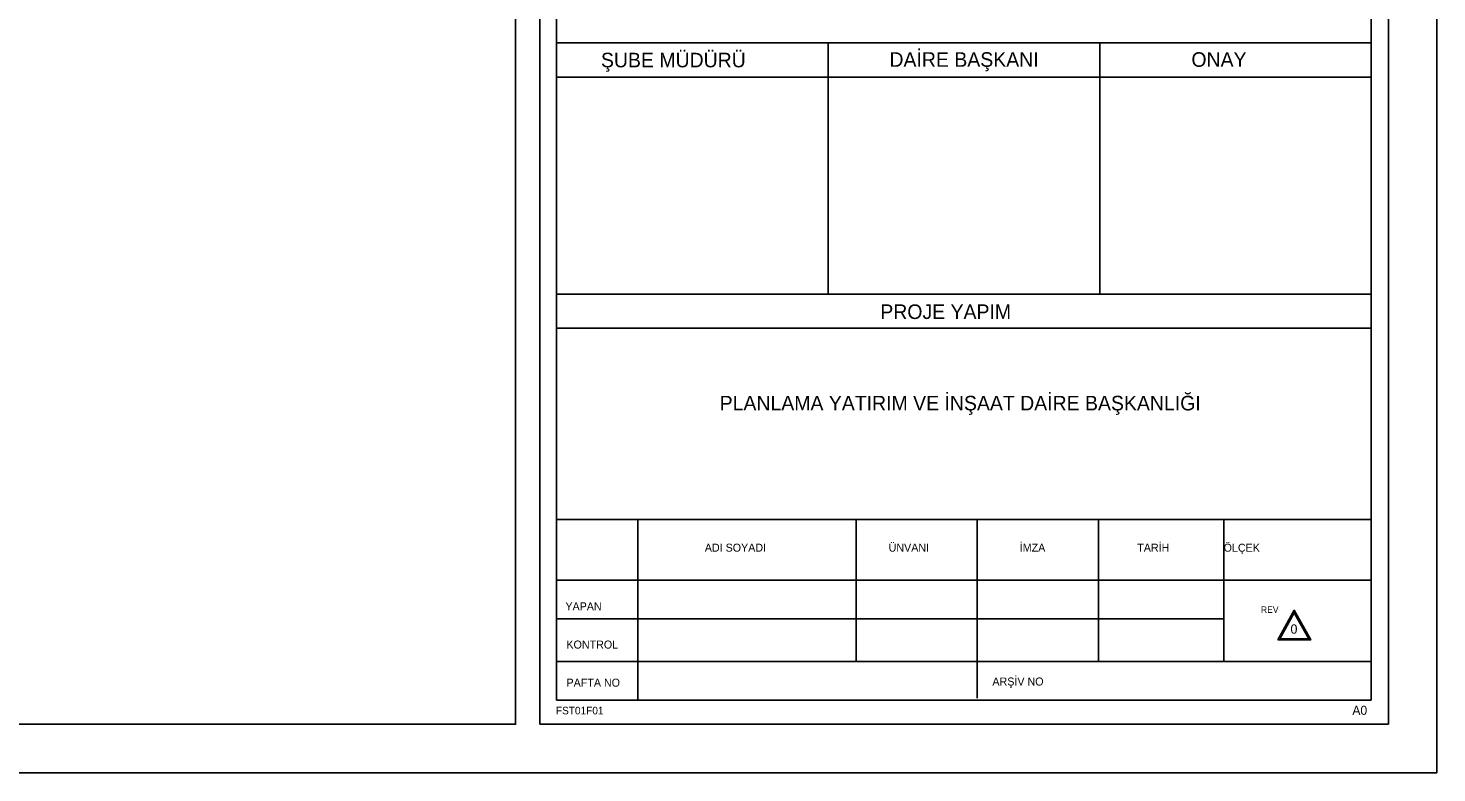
# Model space of a CAD drawing. Extents: x -17 to 1145, y -10 to 821.
# Drawn here: x 854.5 to 1145, y -10 to 143.5 of the extents above; entities that cross this region are included whole.
import ezdxf

# ---------------------------------------------------------------- set-up
doc = ezdxf.new("R2010")
doc.units = 0
for name, color, linetype in [('Level 1', 7, 'Continuous'), ('Level 50', 7, 'Continuous'), ('Level 51', 7, 'Continuous'), ('Level 6', 7, 'Continuous'), ('Level 7', 7, 'Continuous')]:
    doc.layers.add(name, color=color, linetype=linetype)

msp = doc.modelspace()

# ---------------------------------------------------------------- linework, layer by layer
at = {"layer": 'Level 1'}
for p, q in [((960, 0), (960, 287)), ((1135, 287), (1135, 0)), ((1135, 0), (960, 0))]:
    msp.add_line(p, q, dxfattribs=at)
at = {"layer": 'Level 50'}
msp.add_lwpolyline([(-7, 0), (955, 0), (955, 811), (-7, 811)], close=True, dxfattribs=at)
at = {"layer": 'Level 51'}
msp.add_lwpolyline([(-17, -10), (1145, -10), (1145, 821), (-17, 821)], close=True, dxfattribs=at)
at = {"layer": 'Level 6'}
for p, q in [((963.47, 4.97), (963.47, 267.9)), ((1131.45, 4.97), (1131.45, 267.9)), ((1131.45, 4.97), (1131.45, 267.9)), ((1131.45, 4.97), (1131.45, 267.9)), ((1131.45, 4.97), (1131.45, 267.9)), ((963.47, 140.48), (1131.45, 140.48)), ((963.47, 140.48), (1131.45, 140.48)), ((963.47, 140.48), (1131.45, 140.48)), ((963.47, 140.48), (1131.45, 140.48)), ((1019.47, 88.65), (1019.47, 140.48)), ((1075.47, 88.65), (1075.47, 140.48)), ((963.47, 133.4), (1131.45, 133.4)), ((963.47, 133.4), (1131.45, 133.4)), ((963.47, 133.4), (1131.45, 133.4)), ((963.47, 88.65), (1131.45, 88.65)), ((963.47, 88.65), (1131.45, 88.65)), ((963.47, 88.65), (1131.45, 88.65)), ((963.47, 88.65), (1131.45, 88.65)), ((963.47, 81.62), (1131.45, 81.62)), ((963.47, 42.24), (1131.45, 42.24)), ((963.47, 42.24), (1131.45, 42.24)), ((963.47, 42.24), (1131.45, 42.24)), ((963.47, 42.24), (1131.45, 42.24)), ((980.23, 4.97), (980.23, 42.1)), ((1025.23, 13.02), (1025.23, 42.1)), ((1050.23, 5.36), (1050.23, 42.1)), ((1075.23, 12.98), (1075.23, 42.1)), ((1101.07, 42.34), (1101.07, 13.04)), ((963.34, 29.74), (1131.31, 29.74)), ((963.47, 21.72), (1101.07, 21.72)), ((963.47, 12.95), (1131.32, 12.95)), ((963.47, 4.97), (1131.45, 4.97)), ((963.47, 4.97), (1131.45, 4.97)), ((963.47, 4.97), (1131.45, 4.97)), ((963.47, 4.97), (1131.45, 4.97))]:
    msp.add_line(p, q, dxfattribs=at)
at = {"layer": 'Level 7'}
for points in [[(1112.18, 17.38), (1115.59, 23.5), (1119.01, 17.38)], [(1112.18, 17.38), (1115.59, 23.5), (1119.01, 17.38)], [(1112.18, 17.38), (1115.59, 23.5), (1119.01, 17.38)], [(1112.18, 17.38), (1115.59, 23.5), (1119.01, 17.38)], [(1112.6, 17.63), (1115.59, 22.99), (1118.59, 17.63)], [(1112.6, 17.63), (1115.59, 22.99), (1118.59, 17.63)], [(1112.6, 17.63), (1115.59, 22.99), (1118.59, 17.63)], [(1112.6, 17.63), (1115.59, 22.99), (1118.59, 17.63)]]:
    msp.add_lwpolyline(points, close=True, dxfattribs=at)

# ---------------------------------------------------------------- texts
at = {"layer": 'Level 1'}
msp.add_text('0', height=1.92, dxfattribs=at).set_placement((1114.82, 18.67))
at = {"layer": 'Level 7'}
for s, height, p in [('ŞUBE MÜDÜRÜ', 3, (972.62, 135.41)), ('DAİRE BAŞKANI', 3, (1032.12, 135.52)), ('ONAY', 3, (1094.39, 135.52)), ('PROJE YAPIM', 3, (1030.23, 83.54)), ('PLANLAMA YATIRIM VE İNŞAAT DAİRE BAŞKANLIĞI', 3, (997.1, 64.7)), ('ADI SOYADI', 1.65, (994.04, 35.58)), ('ÜNVANI', 1.65, (1031.95, 35.58)), ('İMZA', 1.65, (1058.99, 35.58)), ('TARİH', 1.65, (1083.22, 35.58)), ('ÖLÇEK', 1.65, (1101.03, 35.57)), ('YAPAN', 1.65, (965.29, 23.48)), ('REV', 1.32, (1108.73, 22.97)), ('KONTROL', 1.65, (965.5, 15.61)), ('PAFTA NO', 1.65, (965.52, 7.76)), ('ARŞİV NO', 1.65, (1053.35, 7.99)), ('FST01F01', 1.555, (963.33, 2.05)), ('A0', 1.866, (1127.58, 1.95))]:
    msp.add_text(s, height=height, dxfattribs=at).set_placement(p)

doc.saveas('drawing.dxf')
